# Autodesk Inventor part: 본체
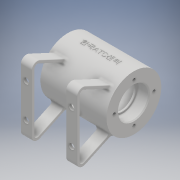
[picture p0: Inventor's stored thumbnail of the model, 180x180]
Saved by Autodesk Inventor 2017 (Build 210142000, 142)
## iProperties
Part Number: 본체
Material: 일반
Document SubType Name: Modeling
Designer: Administrator
Density: 1 g/cm^3
Appearance: 기본값
Author: Administrator
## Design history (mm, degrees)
sketch "스케치3"
  geometry: L1 (0, 29)-(70, 29); L2 (70, 29)-(70, 16); L3 (70, 16)-(58, 16); L4 (58, 16)-(58, 14); L5 (58, 14)-(56, 14); L6 (56, 14)-(56, 21); L7 (56, 21)-(14, 21); L8 (14, 21)-(14, 14); L9 (14, 14)-(12, 14); L10 (12, 14)-(12, 16); L11 (12, 16)-(0, 16); L12 (0, 16)-(0, 29); L13 (0, 0)-(70, 0)
  constraints: 26 end point, 9 perpendicular, 4 point on line, 2 horizontal, 2 vertical alignment
  dimensions: "d1" = 70 distance of L1.start L1.end; "d2" = 58 diameter of L1 L13; "d3" = 32 diameter of L11 L13; "d4" = 28 diameter of L9 L13; "d5" = 42 diameter of L7 L13; "d6" = 12 distance of L10.end L11.end; "d7" = 42 distance of L6.end L7.end; "d8" = 2 distance of L4.end L5.end; "d9" = 2 distance of L8.end L9.end
revolve "회전1" sketch "스케치3" stored, may be unused: angle "d10" = 90 deg
node "작업 평면1"
sketch "스케치5"
  geometry: L1 (0, 29)-(0, -29) reference; C1 r 5 at (-35, 0); 2 further points
  constraints: 1 centre point, 1 horizontal alignment, 1 midpoint
  dimensions: "d12" = 10 diameter of C1; "d13" = 35 distance from line of C1.centre L1
extrude "돌출1" join sketch "스케치5" stored distance "d14" = 10; taper "d15" = 0 deg
sketch "스케치6"
  geometry: 2 further points
  constraints: 1 vertical alignment
  dimensions: "d16" = 21 distance of point (0, 21) point (0, 0)
hole "구멍1" sketch "스케치6" at (0, 21) diameter "d17" = 3.242; stored, may be unused: countersink angle "d21" = 90 deg, drill point angle "d23" = 118 deg; dims "d18" = 8, "d19" = 4, "d20" = 2, "d22" = 10
node "작업 평면2"
node "작업 평면4"
node "작업 평면5"
sketch "스케치9"
  geometry: L1 (-17.993, 22.743)-(-46.464, 36.02); L2 (-55, 30.582)-(-55, -30.582); L3 (-46.464, -36.02)-(-17.993, -22.743); L4 (-20.438, -20.574)-(-47.732, -33.301); L5 (-52, -30.582)-(-52, 30.582); L6 (-47.732, 33.301)-(-20.438, 20.574); A1 r 29 centre (0, 0) between (-17.993, 22.743) and (-17.993, -22.743) reference; A2 r 6 centre (-49, 30.582) between (-46.464, 36.02) and (-55, 30.582); A3 r 6 centre (-49, -30.582) between (-55, -30.582) and (-46.464, -36.02); A4 r 3 centre (-49, -30.582) between (-52, -30.582) and (-47.732, -33.301); A5 r 3 centre (-49, 30.582) between (-47.732, 33.301) and (-52, 30.582); 5 further points
  constraints: 12 end point, 12 point on circle, 4 centre point, 4 point on line, 4 tangent, 2 horizontal alignment, 2 midpoint, 1 equal radius, 1 parallel, 1 vertical, 2 other
  dimensions: "d50" = 80 distance of point (-55, 40) point (-55, -40); "d51" = 55 distance from line of L2 point (0, 0); "d52" = 65 deg angle of L2 L3; "d53" = 65 deg angle of L2 L1; "d54" = 6 radius of A2 (derived); "d55" = 3 distance between parallel lines of L3 L4; "d56" = 3 radial gap between concentric circles of A3 A4; "d57" = 3 distance between parallel lines of L1 L6
extrude "돌출4" join sketch "스케치9" distance "d58" = 12; taper "d59" = 0 deg
sketch "스케치10"
  geometry: L1 (0, 0)-(0, 61.164) reference; L2 (0, -6)-(0, 0) reference; C1 r 3 at (6, 48.582); C2 r 3 at (6, 12.582); 2 further points
  constraints: 2 centre point
  dimensions: "d60" = 6 diameter of C1; "d61" = 6 distance from line of C1.centre L1; "d62" = 6 diameter of C2; "d63" = 6 distance from line of L2 C2.centre; "d64" = 36 distance of C2.centre C1.centre; "d65" = 18 vertical distance of C1.centre point (-5, 30.582)
extrude "돌출5" cut sketch "스케치10" distance "d66" = 12; taper "d67" = 0 deg
sketch "스케치12"
  geometry: L1 (0, 0)-(10.945, -30.07); L2 (0, 0)-(0, -32.292)
  constraints: 4 end point, 1 vertical
  dimensions: "d68" = 32 distance of L1.start L1.end; "d69" = 20 deg angle of L1 L2; "d72" = 32.29204 distance of L1.start L2.end
node "작업 평면6"
sketch "스케치13"
  geometry: L1 (0, -29)-(0, 29) reference; C1 r 6 at (-35, 0); 2 further points
  constraints: 1 centre point, 1 horizontal alignment, 1 midpoint
  dimensions: "d70" = 12 diameter of C1; "d71" = 35 distance from line of C1.centre L1
extrude "돌출6" join sketch "스케치13" stored distance "d73" = 12; taper "d74" = 0 deg
hole "구멍2" diameter "d77" = 5.188; stored, may be unused: countersink angle "d81" = 90 deg, drill point angle "d83" = 118 deg; dims "d75" = 10, "d76" = 10, "d78" = 12, "d79" = 4, "d80" = 2, "d82" = 16
hole "구멍3" diameter "d86" = 5.188; stored, may be unused: countersink angle "d90" = 90 deg, drill point angle "d92" = 118 deg; dims "d84" = 10, "d85" = 10, "d87" = 6, "d88" = 4, "d89" = 2, "d91" = 8
hole "구멍4" diameter "d95" = 3; stored, may be unused: countersink angle "d99" = 90 deg, drill point angle "d101" = 118 deg; dims "d93" = 10, "d94" = 10, "d96" = 6, "d97" = 4, "d98" = 2, "d100" = 30
fillet "모깎기2" dims "d102" = 1
fillet "모깎기3" dims "d103" = 1
fillet "모깎기4" dims "d104" = 0.5
fillet "모깎기5" dims "d105" = 3
fillet "모깎기6" dims "d106" = 3
fillet "모깎기7" dims "d107" = 0.3
chamfer "모따기1" distance "d108" = 1; stored, may be unused: second distance "d109" = 2, angle "d110" = 45 deg
node "작업 평면7"
sketch "스케치14"
  geometry: L1 (0, -29)-(0, 29) reference; L2 (0, 29)-(70, 29) reference; 2 further points
  constraints: 1 other
  dimensions: "d112" = 35 distance from line of point (35, 0) L1; "d113" = 29 distance from line of point (35, 0) L2
feature "엠보싱1" sketch "스케치14" dims "d1" = 70, "d2" = 58, "d3" = 32, "d4" = 28, "d5" = 42, "d6" = 12, "d7" = 42, "d8" = 2, "d9" = 2, "d114" = 0.5, "d115" = 0
node "솔리드1"
pattern_circular "원형 패턴1" dims angle "d25" = 360 deg
mirror "미러1"
mirror "미러2"
other parameters: "d11" = 32, "d27" = 35, "d29" = 5, "d41" = 5, "d111" = 29.5
